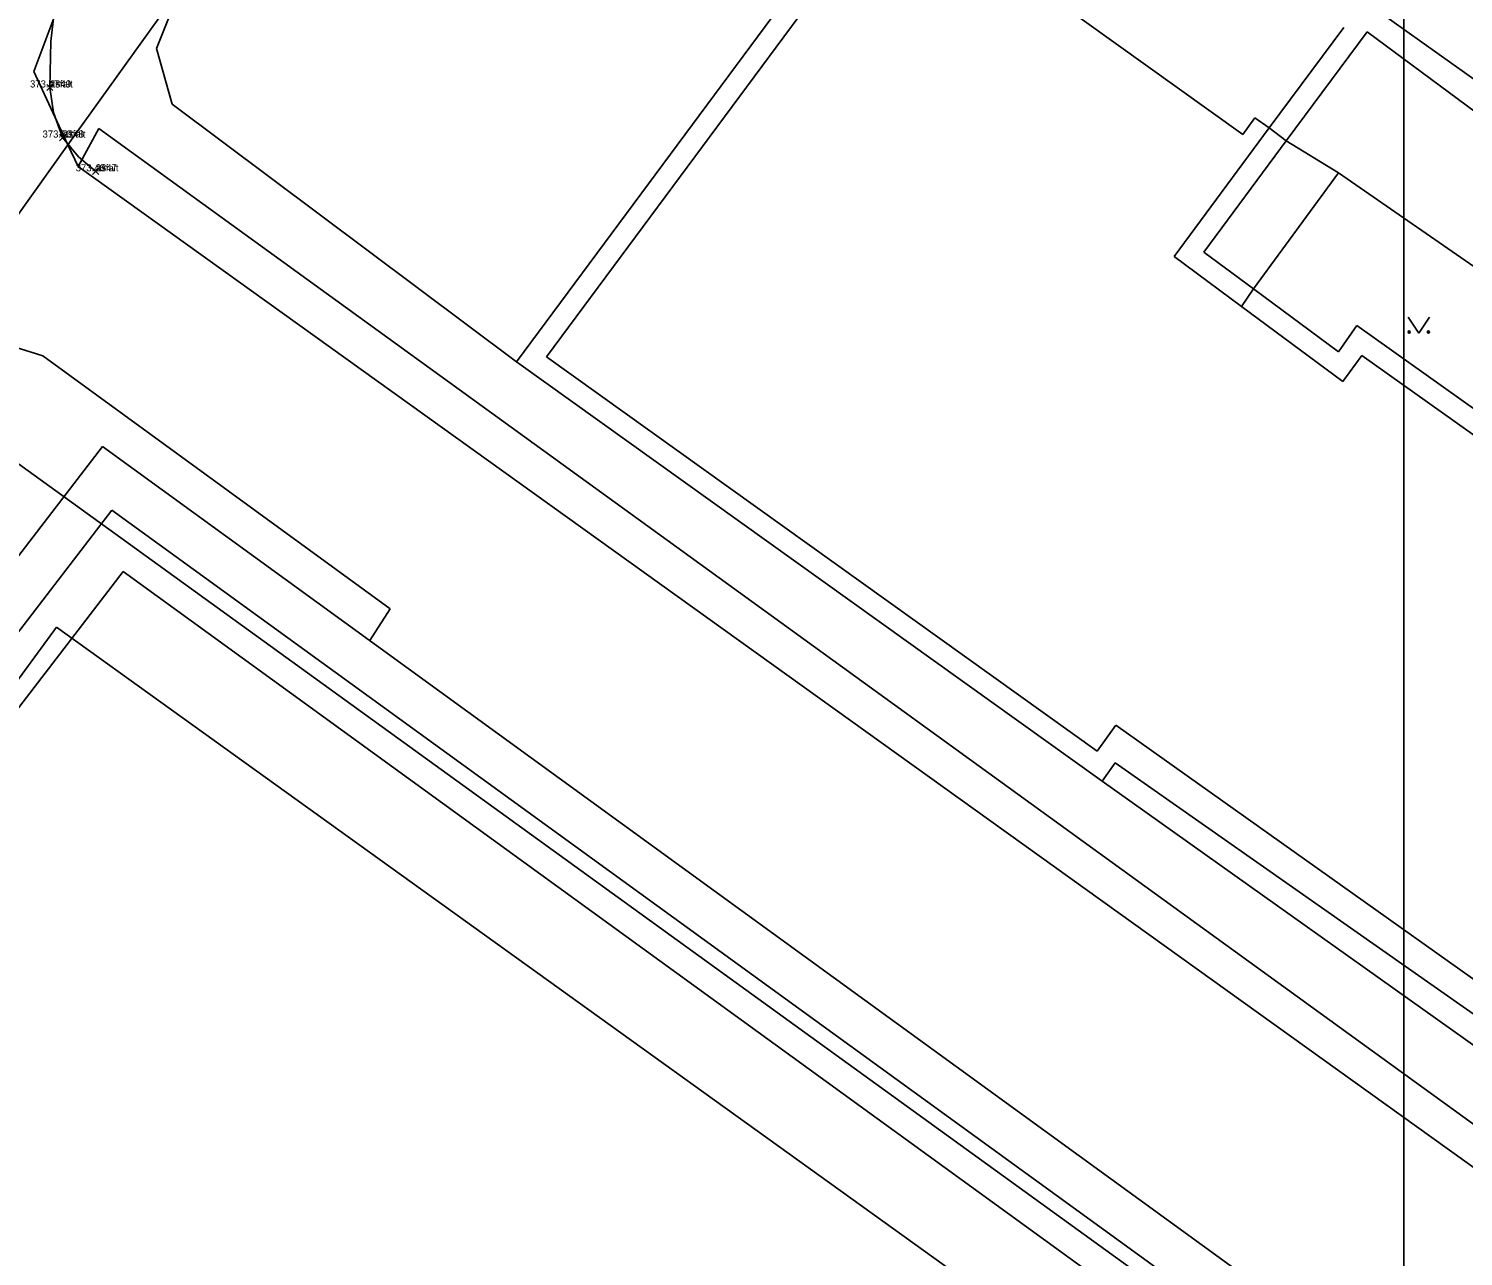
# Model space of a CAD drawing. Extents: x -400488 to -400124, y -1251493 to -1251223.
# Drawn here: x -400289.12 to -400248.76, y -1251434.41 to -1251399.85 of the extents above; entities that cross this region are included whole.
import ezdxf

# ---------------------------------------------------------------- set-up
doc = ezdxf.new("R2010")
doc.units = 0
for name, color, linetype in [('Level 20', 7, 'Continuous'), ('Level 21', 7, 'Continuous'), ('Level 22', 7, 'Continuous'), ('Level 23', 7, 'Continuous'), ('Level 3', 7, 'Continuous'), ('Level 32', 7, 'Continuous'), ('Level 49', 7, 'Continuous'), ('Level 63', 7, 'Continuous')]:
    doc.layers.add(name, color=color, linetype=linetype)

msp = doc.modelspace()

# ---------------------------------------------------------------- linework, layer by layer
at = {"layer": 'Level 20'}
for p, q in [((-400288.608, -1251401.598), (-400288.432, -1251401.422)), ((-400288.432, -1251401.598), (-400288.608, -1251401.422)), ((-400288.248, -1251403.008), (-400288.072, -1251402.832)), ((-400288.072, -1251403.008), (-400288.248, -1251402.832)), ((-400287.318, -1251403.958), (-400287.142, -1251403.782)), ((-400287.142, -1251403.958), (-400287.318, -1251403.782))]:
    msp.add_line(p, q, dxfattribs=at)
at = {"layer": 'Level 3'}
msp.add_lwpolyline([(-400397.431, -1251233.087), (-400250.431, -1251233.087), (-400250.431, -1251440.987), (-400397.431, -1251440.987)], close=True, dxfattribs=at)
at = {"layer": 'Level 32'}
msp.add_lwpolyline([(-400287.23, -1251403.87), (-400287.71, -1251403.463), (-400288.16, -1251402.92), (-400288.414, -1251402.215), (-400288.52, -1251401.51), (-400288.49, -1251400.213), (-400288.36, -1251399.07), (-400288.07, -1251398.42)], dxfattribs=at)
at = {"layer": 'Level 49'}
msp.add_spline([(-400288.181, -1251402.882), (-400288.16, -1251402.92), (-400288.181, -1251402.882)], degree=3, dxfattribs=at)
at = {"layer": 'Level 63'}
for p, q in [((-400265.04, -1251395.26), (-400275.39, -1251409.23)), ((-400275.39, -1251409.23), (-400265.04, -1251395.26)), ((-400264.92, -1251396.1), (-400274.55, -1251409.09)), ((-400287.97, -1251398.37), (-400288.97, -1251401.06)), ((-400288.01, -1251403.12), (-400284.83, -1251398.69)), ((-400284.83, -1251398.69), (-400288.01, -1251403.12)), ((-400284.83, -1251398.69), (-400285.52, -1251400.41)), ((-400285.52, -1251400.41), (-400284.83, -1251398.69)), ((-400254.96, -1251402.83), (-400260.56, -1251398.82)), ((-400260.56, -1251398.82), (-400254.96, -1251402.83)), ((-400248.24, -1251401.44), (-400251.61, -1251399.02)), ((-400254.22, -1251402.65), (-400252.12, -1251399.82)), ((-400251.46, -1251399.94), (-400253.74, -1251403.01)), ((-400253.74, -1251403.01), (-400251.46, -1251399.94)), ((-400248.13, -1251402.41), (-400251.46, -1251399.94)), ((-400251.46, -1251399.94), (-400248.13, -1251402.41)), ((-400285.52, -1251400.41), (-400285.08, -1251401.98)), ((-400285.08, -1251401.98), (-400285.52, -1251400.41)), ((-400288.97, -1251401.06), (-400288.01, -1251403.12)), ((-400285.08, -1251401.98), (-400275.39, -1251409.23)), ((-400275.39, -1251409.23), (-400285.08, -1251401.98)), ((-400254.62, -1251402.36), (-400254.96, -1251402.83)), ((-400254.96, -1251402.83), (-400254.62, -1251402.36)), ((-400254.22, -1251402.65), (-400254.62, -1251402.36)), ((-400254.62, -1251402.36), (-400254.22, -1251402.65)), ((-400287.72, -1251403.73), (-400287.14, -1251402.66)), ((-400287.14, -1251402.66), (-400219.04, -1251452.02)), ((-400254.22, -1251402.65), (-400256.89, -1251406.27)), ((-400253.74, -1251403.01), (-400254.22, -1251402.65)), ((-400254.22, -1251402.65), (-400253.74, -1251403.01)), ((-400291.62, -1251408.17), (-400288.01, -1251403.12)), ((-400288.01, -1251403.12), (-400291.62, -1251408.17)), ((-400288.01, -1251403.12), (-400287.72, -1251403.73)), ((-400253.74, -1251403.01), (-400256.06, -1251406.14)), ((-400256.06, -1251406.14), (-400253.74, -1251403.01)), ((-400253.74, -1251403.01), (-400252.27, -1251403.91)), ((-400287.72, -1251403.73), (-400219.65, -1251452.6)), ((-400254.66, -1251407.18), (-400252.27, -1251403.91)), ((-400252.27, -1251403.91), (-400245.56, -1251408.56)), ((-400256.89, -1251406.27), (-400255, -1251407.67)), ((-400256.06, -1251406.14), (-400254.66, -1251407.18)), ((-400254.66, -1251407.18), (-400256.06, -1251406.14)), ((-400254.66, -1251407.18), (-400255, -1251407.67)), ((-400254.66, -1251407.18), (-400252.27, -1251408.95)), ((-400252.27, -1251408.95), (-400254.66, -1251407.18)), ((-400255, -1251407.67), (-400252.15, -1251409.78)), ((-400250.31, -1251407.97), (-400250.01, -1251408.42)), ((-400250.01, -1251408.42), (-400249.71, -1251407.97)), ((-400291.62, -1251408.17), (-400288.72, -1251409.06)), ((-400252.27, -1251408.95), (-400251.75, -1251408.21)), ((-400251.75, -1251408.21), (-400252.27, -1251408.95)), ((-400251.75, -1251408.21), (-400247.28, -1251411.4)), ((-400247.28, -1251411.4), (-400251.75, -1251408.21)), ((-400288.72, -1251409.06), (-400278.95, -1251416.18)), ((-400275.39, -1251409.23), (-400258.92, -1251421.03)), ((-400258.92, -1251421.03), (-400275.39, -1251409.23)), ((-400274.55, -1251409.09), (-400259.06, -1251420.19)), ((-400252.15, -1251409.78), (-400251.61, -1251409.05)), ((-400251.61, -1251409.05), (-400247.63, -1251411.89)), ((-400250.32, -1251440.37), (-400290.8, -1251411.09)), ((-400290.8, -1251411.09), (-400250.32, -1251440.37)), ((-400300.81, -1251429.57), (-400287.04, -1251411.61)), ((-400287.04, -1251411.61), (-400201.09, -1251474.06)), ((-400300.54, -1251431.36), (-400286.78, -1251413.41)), ((-400286.78, -1251413.41), (-400201.79, -1251475.05)), ((-400286.46, -1251415.13), (-400300.27, -1251433.14)), ((-400203.57, -1251475.28), (-400286.46, -1251415.13)), ((-400278.95, -1251416.18), (-400279.52, -1251417.07)), ((-400288.33, -1251416.7), (-400304.56, -1251438.79)), ((-400259.32, -1251437.56), (-400288.33, -1251416.7)), ((-400259.06, -1251420.19), (-400258.53, -1251419.46)), ((-400258.53, -1251419.46), (-400221.9, -1251445.5)), ((-400258.55, -1251420.52), (-400258.92, -1251421.03)), ((-400258.92, -1251421.03), (-400258.55, -1251420.52)), ((-400222.25, -1251445.99), (-400258.55, -1251420.52)), ((-400258.55, -1251420.52), (-400222.25, -1251445.99)), ((-400258.92, -1251421.03), (-400222.82, -1251446.71)), ((-400222.82, -1251446.71), (-400258.92, -1251421.03))]:
    msp.add_line(p, q, dxfattribs=at)
for centre in [(-400250.28, -1251408.39), (-400249.74, -1251408.39)]:
    msp.add_circle(centre, 0.03, dxfattribs=at)

# ---------------------------------------------------------------- texts
at = {"layer": 'Level 21'}
for s, p in [('2349', (-400288.52, -1251401.51)), ('2348', (-400288.16, -1251402.92)), ('2347', (-400287.23, -1251403.87))]:
    msp.add_text(s, height=0.2, dxfattribs=at).set_placement(p)
at = {"layer": 'Level 22'}
for p in [(-400288.52, -1251401.51), (-400288.16, -1251402.92), (-400287.23, -1251403.87)]:
    msp.add_text('asfalt', height=0.2, dxfattribs=at).set_placement(p)
at = {"layer": 'Level 23'}
for s, p in [('373.47', (-400289.078, -1251401.51)), ('373.50', (-400288.726, -1251402.92)), ('373.46', (-400287.793, -1251403.87))]:
    msp.add_text(s, height=0.2, dxfattribs=at).set_placement(p)

doc.saveas('drawing.dxf')
